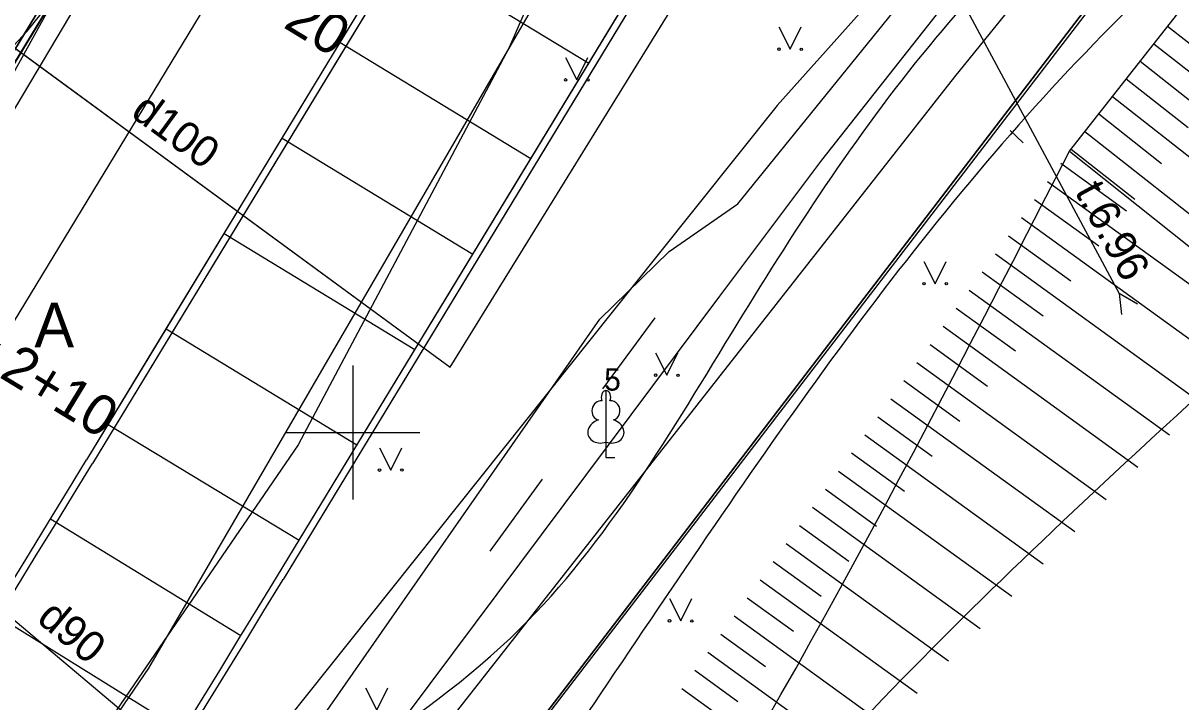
# Model space of a CAD drawing. Extents: x 514086 to 514457, y 297399 to 297567.
# Drawn here: x 514292.61 to 514318.55, y 297493.97 to 297509.16 of the extents above; entities that cross this region are included whole.
import ezdxf

# ---------------------------------------------------------------- set-up
doc = ezdxf.new("R2010")
doc.units = 0
for name, color, linetype in [('AA_Brauktuve', 7, 'Continuous'), ('AA_Brugis_stavvietas', 7, 'Continuous'), ('AA_cela_mala', 7, 'Continuous'), ('AA_Ielas_ass', 7, 'Continuous'), ('AA_Ietve', 7, 'Continuous'), ('AA_Stavvietas', 7, 'Continuous'), ('AA_Zale', 7, 'Continuous'), ('Level 1', 7, 'Continuous'), ('Level 11', 7, 'Continuous'), ('Level 17', 7, 'Continuous'), ('Level 23', 7, 'Continuous'), ('Level 29', 7, 'Continuous'), ('Level 30', 7, 'Continuous'), ('Level 31', 7, 'Continuous'), ('Level 32', 7, 'Continuous'), ('Level 35', 7, 'Continuous'), ('Level 36', 7, 'Continuous'), ('Level 37', 7, 'Continuous'), ('Level 41', 7, 'Continuous'), ('Level 42', 7, 'Continuous'), ('Level 45', 7, 'Continuous'), ('Level 46', 7, 'Continuous'), ('Level 61', 7, 'Continuous'), ('Level 8', 7, 'Continuous')]:
    doc.layers.add(name, color=color, linetype=linetype)

msp = doc.modelspace()

# ---------------------------------------------------------------- linework, layer by layer
at = {"layer": 'AA_Brauktuve'}
for points in [[(514308.7, 297535.066), (514288.91, 297502.503)], [(514294.038, 297499.387), (514294.522, 297500.183), (514295.82, 297502.32), (514297.119, 297504.456), (514298.417, 297506.593), (514299.715, 297508.729), (514301.014, 297510.865), (514302.572, 297513.429), (514304.13, 297515.993), (514305.688, 297518.557), (514307.506, 297521.548)]]:
    msp.add_lwpolyline(points, dxfattribs=at)
msp.add_arc((513864.192, 297760.618), 503, 322.75294, 328.71151, dxfattribs=at)
at = {"layer": 'AA_Brugis_stavvietas'}
for points in [[(514307.36, 297521.019), (514294.166, 297499.309)], [(514298.31, 297496.79), (514311.259, 297518.096), (514307.841, 297520.174)]]:
    msp.add_lwpolyline(points, dxfattribs=at)
for radius in [503.15, 508]:
    msp.add_arc((513864.192, 297760.618), radius, 322.75294, 328.71151, dxfattribs=at)
at = {"layer": 'AA_cela_mala'}
for p, q in [((514288.91, 297502.503), (514308.7, 297535.066)), ((514294.038, 297499.387), (514307.506, 297521.548)), ((514307.36, 297521.019), (514294.166, 297499.309)), ((514298.31, 297496.79), (514311.259, 297518.096)), ((514311.465, 297518.147), (514298.439, 297496.712)), ((514293.581, 297510.477), (514290.302, 297505.082))]:
    msp.add_line(p, q, dxfattribs=at)
for radius in [503, 503.15, 508, 508.15]:
    msp.add_arc((513864.192, 297760.618), radius, 322.75294, 328.71151, dxfattribs=at)
at = {"layer": 'AA_Ielas_ass'}
msp.add_line((514291.474, 297500.945), (514311.288, 297533.548), dxfattribs=at)
at = {"layer": 'AA_Ietve'}
msp.add_line((514288.782, 297502.581), (514308.572, 297535.144), dxfattribs=at)
at = {"layer": 'AA_Stavvietas'}
for p, q in [((514301.014, 297510.865), (514305.287, 297508.269)), ((514299.715, 297508.729), (514303.988, 297506.132)), ((514298.417, 297506.593), (514302.69, 297503.996)), ((514297.119, 297504.456), (514301.391, 297501.86)), ((514295.82, 297502.32), (514300.093, 297499.723)), ((514294.522, 297500.183), (514298.795, 297497.587)), ((514297.494, 297495.452), (514293.229, 297498.061)), ((514296.184, 297493.322), (514291.932, 297495.953))]:
    msp.add_line(p, q, dxfattribs=at)
at = {"layer": 'AA_Zale'}
msp.add_line((514283.198, 297466.177), (514325.029, 297520.708), dxfattribs=at)
for points in [[(514236.652, 297413.496), (514237.314, 297412.963), (514250.581, 297429.476), (514253.4, 297427.333), (514283.198, 297466.177), (514325.029, 297520.708), (514327.112, 297523.423), (514336.853, 297525.444), (514334.256, 297529.664)], [(514307.919, 297520.302), (514311.465, 297518.147), (514298.439, 297496.712)]]:
    msp.add_lwpolyline(points, dxfattribs=at)
msp.add_arc((513864.192, 297760.618), 508.15, 322.75294, 328.71151, dxfattribs=at)
at = {"layer": 'Level 1'}
for p, q in [((514305.672, 297499.786), (514305.672, 297499.439)), ((514305.672, 297499.439), (514305.872, 297499.439))]:
    msp.add_line(p, q, dxfattribs=at)
for points in [[(514325.349, 297522.592), (514313.48, 297507.964), (514284.691, 297471.315), (514272.976, 297455.563)], [(514305.672, 297500.939), (514305.672, 297499.786)], [(514305.762, 297500.707), (514305.761, 297500.708)]]:
    msp.add_lwpolyline(points, dxfattribs=at)
for centre, major_axis, ratio, start_param, end_param in [((514305.672, 297500.789), (0, -0.15), 0.707107, 3.14537, 5.287485), ((514305.672, 297500.789), (0, -0.15), 0.707107, 0.995701, 3.137816), ((514305.544, 297500.494), (-0.039, -0.212), 0.861323, 3.141593, 6.283185), ((514305.8, 297500.494), (0.039, -0.212), 0.861323, 0, 3.141593), ((514305.582, 297500.032), (0.307, 0.095), 0.814445, 1.570796, 4.752015), ((514305.762, 297500.032), (-0.307, 0.095), 0.814445, 1.531171, 4.712389)]:
    msp.add_ellipse(centre, major_axis=major_axis, ratio=ratio, start_param=start_param, end_param=end_param, dxfattribs=at)
at = {"layer": 'Level 11'}
for p, q in [((514308.648, 297518.974), (514317.172, 297503.111)), ((514317.58, 297502.873), (514317.172, 297503.111)), ((514317.172, 297503.111), (514317.22, 297502.641))]:
    msp.add_line(p, q, dxfattribs=at)
at = {"layer": 'Level 17'}
msp.add_line((514288.467, 297511.508), (514302.185, 297501.461), dxfattribs=at)
msp.add_lwpolyline([(514282.572, 297503.806), (514288.467, 297511.508), (514295.326, 297506.485), (514302.185, 297501.461), (514317.671, 297526.51), (514327.071, 297531.454), (514337.273, 297536.82), (514349.958, 297543.491), (514353.979, 297547.673)], dxfattribs=at)
at = {"layer": 'Level 23'}
for p, q in [((514309.548, 297509.082), (514309.798, 297508.582)), ((514309.798, 297508.582), (514310.048, 297509.082)), ((514304.769, 297508.394), (514305.019, 297507.894)), ((514305.019, 297507.894), (514305.269, 297508.394)), ((514312.796, 297503.831), (514313.046, 297503.331)), ((514313.046, 297503.331), (514313.296, 297503.831)), ((514306.784, 297501.784), (514307.034, 297501.284)), ((514307.034, 297501.284), (514307.284, 297501.784)), ((514300.6, 297499.659), (514300.85, 297499.159)), ((514300.85, 297499.159), (514301.1, 297499.659)), ((514307.096, 297496.284), (514307.346, 297495.784)), ((514307.346, 297495.784), (514307.596, 297496.284)), ((514300.287, 297494.284), (514300.537, 297493.784)), ((514300.537, 297493.784), (514300.787, 297494.284))]:
    msp.add_line(p, q, dxfattribs=at)
for centre, radius in [((514309.548, 297508.581), 0.028), ((514310.048, 297508.581), 0.0263), ((514304.769, 297507.894), 0.028), ((514305.269, 297507.894), 0.0263), ((514312.796, 297503.331), 0.028), ((514313.296, 297503.331), 0.0263), ((514306.784, 297501.284), 0.028), ((514307.284, 297501.284), 0.0263), ((514300.599, 297499.159), 0.028), ((514301.099, 297499.159), 0.0263), ((514307.096, 297495.784), 0.028), ((514307.596, 297495.784), 0.0263)]:
    msp.add_circle(centre, radius, dxfattribs=at)
at = {"layer": 'Level 29'}
for p, q in [((514325.029, 297520.708), (514241.366, 297411.646)), ((514293.669, 297510.358), (514285.885, 297496.27))]:
    msp.add_line(p, q, dxfattribs=at)
at = {"layer": 'Level 30'}
for p, q in [((514300, 297501.5), (514300, 297500)), ((514298.5, 297500), (514300, 297500)), ((514300, 297500), (514300, 297498.5)), ((514300, 297500), (514301.5, 297500))]:
    msp.add_line(p, q, dxfattribs=at)
at = {"layer": 'Level 31'}
for p, q in [((514315.861, 297506.027), (514317.333, 297504.963)), ((514315.568, 297505.621), (514320.414, 297502.121)), ((514315.275, 297505.216), (514316.711, 297504.179)), ((514314.982, 297504.811), (514319.708, 297501.397)), ((514314.689, 297504.405), (514316.089, 297503.394)), ((514314.397, 297504), (514319.001, 297500.674)), ((514314.104, 297503.595), (514315.467, 297502.61)), ((514313.811, 297503.189), (514318.295, 297499.951)), ((514313.518, 297502.784), (514314.845, 297501.826)), ((514313.226, 297502.379), (514317.588, 297499.227)), ((514312.933, 297501.974), (514314.223, 297501.041)), ((514312.64, 297501.568), (514316.882, 297498.504)), ((514312.347, 297501.163), (514313.602, 297500.257)), ((514312.054, 297500.758), (514316.175, 297497.781)), ((514311.762, 297500.352), (514312.98, 297499.472)), ((514311.469, 297499.947), (514315.469, 297497.057)), ((514311.176, 297499.542), (514312.358, 297498.688)), ((514310.883, 297499.136), (514314.763, 297496.334)), ((514310.59, 297498.731), (514311.736, 297497.903)), ((514310.298, 297498.326), (514314.056, 297495.611)), ((514310.005, 297497.92), (514311.114, 297497.119)), ((514309.712, 297497.515), (514313.35, 297494.887)), ((514309.419, 297497.11), (514310.493, 297496.335)), ((514309.127, 297496.704), (514312.643, 297494.164)), ((514308.834, 297496.299), (514309.871, 297495.55)), ((514308.541, 297495.894), (514311.937, 297493.441)), ((514308.248, 297495.488), (514309.249, 297494.766)), ((514307.955, 297495.083), (514311.231, 297492.717)), ((514307.663, 297494.678), (514308.627, 297493.981)), ((514307.37, 297494.273), (514310.524, 297491.994))]:
    msp.add_line(p, q, dxfattribs=at)
msp.add_spline([(514238.182, 297404.63), (514268.566, 297443.685), (514271.22, 297450.146), (514276.219, 297454.734), (514284.527, 297466.568), (514290.967, 297471.565), (514316.058, 297506.3)], degree=3, dxfattribs=at)
at = {"layer": 'Level 32'}
msp.add_line((514314.729, 297506.761), (514315.02, 297506.486), dxfattribs=at)
msp.add_spline([(514321.954, 297513.799), (514315.665, 297507.71), (514304.919, 297493.222), (514302.22, 297489.529), (514296.552, 297484.063), (514293.92, 297480.636), (514293.775, 297479.526), (514293.484, 297478.389), (514290.105, 297476.03), (514288.603, 297473.324), (514288.233, 297471.034), (514286.104, 297469.237), (514283.964, 297468.854), (514283.423, 297470.519), (514284.598, 297472.872), (514289.498, 297479.331), (514295.836, 297489.424), (514303.534, 297495.399), (514308.484, 297502.218), (514312.919, 297508.652), (514317.614, 297514.163), (514324.249, 297524.153), (514327.127, 297525.911), (514330.479, 297525.495), (514338.994, 297522.069)], degree=3, dxfattribs=at)
at = {"layer": 'Level 35'}
msp.add_line((514325.114, 297520.693), (514303.579, 297492.661), dxfattribs=at)
at = {"layer": 'Level 36'}
msp.add_spline([(514320.804, 297502.52), (514306.724, 297488.103), (514301.133, 297479.973), (514270.315, 297441.123), (514246.087, 297412.115), (514239.566, 297403.275)], degree=3, dxfattribs=at)
at = {"layer": 'Level 37'}
msp.add_lwpolyline([(514303.497, 297508.608), (514298.773, 297499.722), (514286.392, 297481.668), (514269.292, 297456.69), (514262.842, 297447.219), (514253.266, 297433.337)], dxfattribs=at)
for points in [[(514331.99, 297531.295), (514330.267, 297531.837), (514329.163, 297532.042), (514328.062, 297532.137), (514326.965, 297532.121), (514325.273, 297531.948), (514323.584, 297531.645), (514321.899, 297531.2), (514320.221, 297530.603), (514319.204, 297530.159), (514318.247, 297529.666), (514317.331, 297529.108), (514316.44, 297528.469), (514315.34, 297527.522), (514314.336, 297526.506), (514313.382, 297525.454), (514312.429, 297524.398), (514303.497, 297508.608)], [(514280.066, 297511.062), (514284.405, 297507.846), (514289.249, 297507.105), (514292.178, 297508.453), (514293.691, 297510.329)]]:
    msp.add_spline(points, degree=3, dxfattribs=at)
at = {"layer": 'Level 41'}
for p, q in [((514318.256, 297509.096), (514322.76, 297505.555)), ((514317.947, 297508.703), (514319.309, 297507.632)), ((514317.638, 297508.31), (514322.216, 297504.71)), ((514317.329, 297507.917), (514318.714, 297506.828)), ((514317.02, 297507.524), (514321.672, 297503.866)), ((514316.711, 297507.131), (514318.118, 297506.025)), ((514316.402, 297506.738), (514321.127, 297503.022)), ((514316.058, 297506.3), (514320.804, 297502.52)), ((514316.093, 297506.344), (514317.522, 297505.221))]:
    msp.add_line(p, q, dxfattribs=at)
msp.add_lwpolyline([(514316.058, 297506.3), (514321.156, 297512.784), (514326.255, 297519.268), (514328.858, 297520.81), (514341.081, 297510.297), (514338.552, 297506.086)], dxfattribs=at)
at = {"layer": 'Level 42'}
for p, q in [((514305.603, 297500.975), (514306.771, 297502.57)), ((514303.077, 297497.343), (514304.252, 297498.956))]:
    msp.add_line(p, q, dxfattribs=at)
at = {"layer": 'Level 45'}
msp.add_lwpolyline([(514298.69, 297492.716), (514305.536, 297502.541), (514307.087, 297504.053), (514308.624, 297505.121), (514313.29, 297510.873), (514316.34, 297514.827)], dxfattribs=at)
at = {"layer": 'Level 46'}
msp.add_lwpolyline([(514139.134, 297486.37), (514229.261, 297420.493), (514237.863, 297414.208), (514250.009, 297428.181), (514295.433, 297494.723), (514312.775, 297524.542), (514316.491, 297528.738), (514320.446, 297531.016), (514328.236, 297532.215), (514332.539, 297530.572), (514332.631, 297530.536), (514341.642, 297542.18), (514320.211, 297553.997), (514285.885, 297496.27), (514243.195, 297433.696), (514241.534, 297432.407), (514239.451, 297432.203), (514209.969, 297445.237), (514194.45, 297457.413), (514175.859, 297473.677), (514139.316, 297503.122), (514133.046, 297508.174), (514130.604, 297489.221)], close=True, dxfattribs=at)
at = {"layer": 'Level 61'}
msp.add_lwpolyline([(514228.605, 297413.892), (514229.168, 297414.699), (514234.462, 297409.66), (514239.192, 297415.557), (514243.591, 297423.09), (514250.856, 297428.146), (514250.871, 297429.329), (514257.62, 297437.772), (514268.028, 297450.791), (514271.687, 297455.368), (514283.043, 297472.127), (514296.63, 297489.788), (514299.744, 297491.72), (514308.223, 297503.049), (514310.505, 297506.097), (514314.057, 297510.598), (514322.921, 297521.831), (514325.028, 297524.077), (514326.601, 297524.074), (514327.377, 297523.947), (514343.661, 297512.323), (514343.876, 297512.066)], dxfattribs=at)
at = {"layer": 'Level 8'}
msp.add_lwpolyline([(514363.513, 297540.75), (514360.351, 297536.898), (514359.482, 297535.839), (514353.406, 297525.223), (514345.234, 297514.353), (514328.27, 297528.306), (514319.28, 297518.25), (514313.196, 297511.446), (514309.505, 297507.318), (514306.815, 297503.948), (514300.399, 297495.913), (514297.136, 297491.825), (514286.021, 297501.175)], dxfattribs=at)

# ---------------------------------------------------------------- texts
at = {"layer": 'AA_Ielas_ass'}
for s, rotation, p in [(' 2+20', 328.6311, (514296.96, 297509.972)), (' 2+10', 328.7115, (514291.767, 297501.427))]:
    msp.add_text(s, height=0.9, rotation=rotation, dxfattribs=at).set_placement(p)
at = {"layer": 'Level 1'}
msp.add_text(' 5', height=0.5, dxfattribs=at).set_placement((514305.447, 297500.939))
at = {"layer": 'Level 11'}
msp.add_text('t.6.96', height=0.7, rotation=298.2514, dxfattribs=at).set_placement((514316.164, 297505.395))
at = {"layer": 'Level 17'}
msp.add_text('d100', height=0.7, rotation=323.7811, dxfattribs=at).set_placement((514294.997, 297507.097))
at = {"layer": 'Level 37'}
msp.add_text('A', height=1, dxfattribs=at).set_placement((514292.865, 297501.905))
at = {"layer": 'Level 8'}
msp.add_text('d90', height=0.7, rotation=319.9286, dxfattribs=at).set_placement((514292.891, 297495.788))

doc.saveas('drawing.dxf')
